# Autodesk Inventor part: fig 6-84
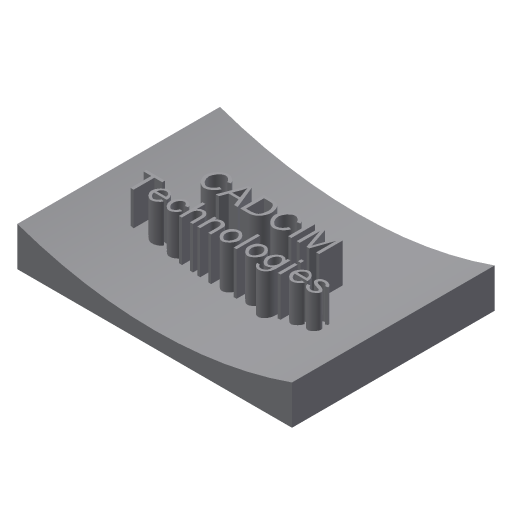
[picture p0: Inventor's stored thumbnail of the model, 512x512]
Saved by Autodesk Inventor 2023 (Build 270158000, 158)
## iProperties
Part Number: fig 6-84
Document SubType Name: Modeling
Created: 2002-12
Designer: deepak
Density: 1 g/cm^3
Material: Generic
Appearance: Default
Control State: 0
Master: False
Checked Out: False
Shininess: 64.0
Length Units: 11269
Angle Units: 11279
Time Units: 11290
Mass Units: 11283
Length Display Precision: 3
Angle Display Precision: 2
Compacted: True
Density: 0.0
Volumn: 0.0
Area: 0.0
PropertySet Name: Model Information
Author: deepak
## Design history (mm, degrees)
sketch "Sketch1"
  geometry: L1 (-39.922, 33.786)-(30.103, 33.786); L2 (30.103, 33.786)-(30.103, -17.894); L3 (30.103, -17.894)-(-39.922, -17.894); L4 (-39.922, -17.894)-(-39.922, 33.786)
  constraints: 8 end point, 2 parallel, 1 horizontal, 1 perpendicular
extrude "Extrusion1" new body sketch "Sketch1" distance "d0" = 10; taper "d1" = 0 deg
workplane "Work Plane1"
sketch "Sketch2"
  geometry: L1 (-37.656, 15.034)-(26.28, 15.034); L2 (26.28, 15.034)-(26.28, 10.168); L3 (26.28, 10.168)-(-37.656, 10.168); L4 (-37.656, 10.168)-(-37.656, 15.034)
  constraints: 2 other
sketch "Sketch3"
  geometry: L1 (70.026, 10)-(0, 10) reference; A1 r 105 centre (35.013, 108.99) between (0, 10) and (70.026, 10)
  constraints: 2 point on circle, 1 centre point
  dimensions: "d5" = 105 radius of A1
extrude "Extrusion2" cut sketch "Sketch3" extent not by distance; stored distance "d3" = 10; taper "d4" = 0 deg
emboss "Emboss4" sketch "Sketch2" dims "d14" = 1, "d15" = 0
body "Solid1"
other parameters: "d2" = 5
